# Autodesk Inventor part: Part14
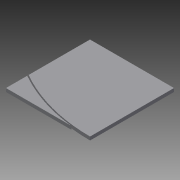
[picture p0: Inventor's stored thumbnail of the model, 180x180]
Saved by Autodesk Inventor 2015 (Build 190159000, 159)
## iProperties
Created: 2015-04
Part Number: Part14
Material: Generic
Document SubType Name: Modeling
Designer: TREINA5
Density: 1 g/cm^3
Appearance: Default
Mass: 129795 g
Surface Area: 48265 cm^2
Volume: 129795 cm^3
Author: TREINA5
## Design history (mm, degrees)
sketch "Sketch1"
  geometry: L1 (10898.159, 7499.198)-(11979.983, 7499.198); L2 (10500, 7499.198)-(10874.958, 7499.198); L3 (10500, 7479.198)-(10886.462, 7479.198); L4 (10909.766, 7479.198)-(11979.983, 7479.198); L5 (10500, 6000)-(10500, 7480); L6 (11979.983, 5999.198)-(10499.983, 5999.198); L7 (11979.983, 5999.198)-(10499.983, 5999.198); L8 (11979.983, 5999.198)-(11979.983, 6386.041); L9 (12000, 6374.536)-(12000, 5999.198); L10 (10499.983, 7479.198)-(10499.983, 5999.198); L11 (10499.983, 7479.198)-(10499.983, 5999.198); L12 (13149.912, 5999.198)-(11999.983, 5999.198); L13 (13149.912, 5999.198)-(11999.983, 5999.198); L14 (11979.983, 6409.341)-(11979.983, 7479.198); L15 (12000, 7479.198)-(12000, 6397.733); L16 (13479.814, 7479.198)-(13479.998, 6000.083); L17 (12000, 7479.198)-(13479.814, 7479.198); L18 (11940.002, 8980)-(11979.983, 8980); L19 (11979.983, 7499.198)-(11979.983, 8980); L20 (10701.515, 8980)-(11940.002, 8980); L21 (10500, 8980)-(10740.282, 8980); L22 (10500, 8642.5)-(10500, 7499.198); A1 r 3010.067 centre (13489.917, 8990) between (10886.462, 7479.198) and (11979.983, 6386.041); A2 r 2989.933 centre (13489.917, 8990) between (10909.766, 7479.198) and (11979.983, 6409.341); A3 r 3010.067 centre (13489.917, 8990) between (12000, 6374.536) and (13149.912, 5999.198); A4 r 2989.933 centre (13489.917, 8990) between (12000, 6397.733) and (13479.998, 6000.083); A5 r 2989.933 centre (13489.917, 8990) between (10500, 8980) and (10898.159, 7499.198); A6 r 3010.067 centre (13489.917, 8990) between (10500, 8642.293) and (10874.958, 7499.198); 1 further point
  constraints: 44 end point, 12 point on circle, 6 centre point, 6 point on line
extrude "Extrusion1" new body sketch "Sketch1" distance "d0" = 60; taper "d1" = 0 deg
extrude "Extrusion2" new body sketch "Sketch1" distance "d2" = 60; taper "d3" = 0 deg
body "Solid1"
body "Solid2"
